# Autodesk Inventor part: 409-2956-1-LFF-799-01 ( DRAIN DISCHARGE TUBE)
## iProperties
Created: 2010-11
Part Number: 409-2956-1-LFF-799-01 ( DRAIN DISCHARGE TUBE)
Material: 3/4" OD TUBE - SS
Document SubType Name: Modeling
Designer: S. Boerckel
Engineer: Steve Boerckel
Mass: 55.5632 g
Surface Area: 85.1076 cm^2
Volume: 6.87664 cm^3
Density: 8.08 g/cm^3
Author: S. Boerckel
Revision Number: 0
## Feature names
1. Extrusion1
